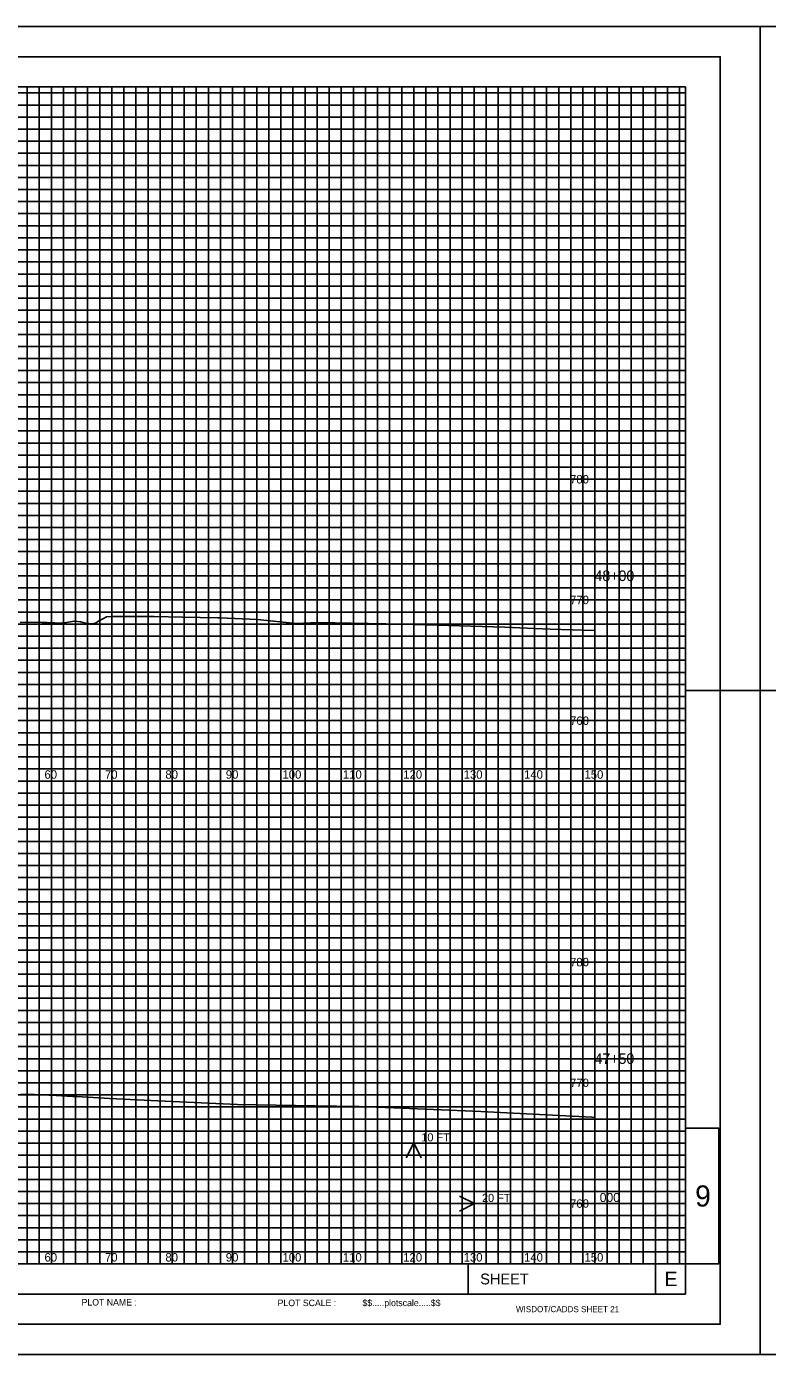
# Model space of a CAD drawing. Extents: x 578243 to 601557, y 174899 to 175559.
# Drawn here: x 600075.7 to 600198.4, y 175338.8 to 175558.8 of the extents above; entities that cross this region are included whole.
import ezdxf

# ---------------------------------------------------------------- set-up
doc = ezdxf.new("R2010")
doc.units = 0
for name, color, linetype in [('E_PROF_Grid', 7, 'Continuous'), ('E_PROF_GridMin', 7, 'Continuous'), ('P_E_XS_Ground', 7, 'Continuous'), ('P_XS_Text', 7, 'Continuous'), ('PLT_Sheet_Border', 7, 'Continuous'), ('PLT_Sheet_Info', 7, 'Continuous')]:
    doc.layers.add(name, color=color, linetype=linetype)

msp = doc.modelspace()

# ---------------------------------------------------------------- linework, layer by layer
at = {"layer": 'E_PROF_Grid'}
for p, q in [((600079.84, 175353.8), (600079.84, 175548.8)), ((600089.84, 175353.8), (600089.84, 175548.8)), ((600099.84, 175353.8), (600099.84, 175548.8)), ((600109.84, 175353.8), (600109.84, 175548.8)), ((600119.84, 175353.8), (600119.84, 175548.8)), ((600129.84, 175353.8), (600129.84, 175548.8)), ((600139.84, 175353.8), (600139.84, 175548.8)), ((600149.84, 175353.8), (600149.84, 175548.8)), ((600159.84, 175353.8), (600159.84, 175548.8)), ((600169.84, 175353.8), (600169.84, 175548.8)), ((600179.84, 175353.8), (600179.84, 175548.8)), ((599869.84, 175543.8), (600184.84, 175543.8)), ((599869.84, 175533.8), (600184.84, 175533.8)), ((599869.84, 175523.8), (600184.84, 175523.8)), ((599869.84, 175513.8), (600184.84, 175513.8)), ((599869.84, 175503.8), (600184.84, 175503.8)), ((599869.84, 175493.8), (600184.84, 175493.8)), ((599869.84, 175483.8), (600184.84, 175483.8)), ((599869.84, 175473.8), (600184.84, 175473.8)), ((599869.84, 175463.8), (600184.84, 175463.8)), ((599869.84, 175453.8), (600184.84, 175453.8)), ((599869.84, 175443.8), (600184.84, 175443.8)), ((599869.84, 175433.8), (600184.84, 175433.8)), ((599869.84, 175423.8), (600184.84, 175423.8)), ((599869.84, 175413.8), (600184.84, 175413.8)), ((599869.84, 175403.8), (600184.84, 175403.8)), ((599869.84, 175393.8), (600184.84, 175393.8)), ((599869.84, 175383.8), (600184.84, 175383.8)), ((599869.84, 175373.8), (600184.84, 175373.8)), ((599869.84, 175363.8), (600184.84, 175363.8))]:
    msp.add_line(p, q, dxfattribs=at)
at = {"layer": 'E_PROF_GridMin'}
for p, q in [((599869.84, 175547.8), (600184.84, 175547.8)), ((600075.84, 175353.8), (600075.84, 175548.8)), ((600077.84, 175353.8), (600077.84, 175548.8)), ((600081.84, 175353.8), (600081.84, 175548.8)), ((600083.84, 175353.8), (600083.84, 175548.8)), ((600085.84, 175353.8), (600085.84, 175548.8)), ((600087.84, 175353.8), (600087.84, 175548.8)), ((600091.84, 175353.8), (600091.84, 175548.8)), ((600093.84, 175353.8), (600093.84, 175548.8)), ((600095.84, 175353.8), (600095.84, 175548.8)), ((600097.84, 175353.8), (600097.84, 175548.8)), ((600101.84, 175353.8), (600101.84, 175548.8)), ((600103.84, 175353.8), (600103.84, 175548.8)), ((600105.84, 175353.8), (600105.84, 175548.8)), ((600107.84, 175353.8), (600107.84, 175548.8)), ((600111.84, 175353.8), (600111.84, 175548.8)), ((600113.84, 175353.8), (600113.84, 175548.8)), ((600115.84, 175353.8), (600115.84, 175548.8)), ((600117.84, 175353.8), (600117.84, 175548.8)), ((600121.84, 175353.8), (600121.84, 175548.8)), ((600123.84, 175353.8), (600123.84, 175548.8)), ((600125.84, 175353.8), (600125.84, 175548.8)), ((600127.84, 175353.8), (600127.84, 175548.8)), ((600131.84, 175353.8), (600131.84, 175548.8)), ((600133.84, 175353.8), (600133.84, 175548.8)), ((600135.84, 175353.8), (600135.84, 175548.8)), ((600137.84, 175353.8), (600137.84, 175548.8)), ((600141.84, 175353.8), (600141.84, 175548.8)), ((600143.84, 175353.8), (600143.84, 175548.8)), ((600145.84, 175353.8), (600145.84, 175548.8)), ((600147.84, 175353.8), (600147.84, 175548.8)), ((600151.84, 175353.8), (600151.84, 175548.8)), ((600153.84, 175353.8), (600153.84, 175548.8)), ((600155.84, 175353.8), (600155.84, 175548.8)), ((600157.84, 175353.8), (600157.84, 175548.8)), ((600161.84, 175353.8), (600161.84, 175548.8)), ((600163.84, 175353.8), (600163.84, 175548.8)), ((600165.84, 175353.8), (600165.84, 175548.8)), ((600167.84, 175353.8), (600167.84, 175548.8)), ((600171.84, 175353.8), (600171.84, 175548.8)), ((600173.84, 175353.8), (600173.84, 175548.8)), ((600175.84, 175353.8), (600175.84, 175548.8)), ((600177.84, 175353.8), (600177.84, 175548.8)), ((600181.84, 175353.8), (600181.84, 175548.8)), ((600183.84, 175353.8), (600183.84, 175548.8)), ((599869.84, 175545.8), (600184.84, 175545.8)), ((599869.84, 175541.8), (600184.84, 175541.8)), ((599869.84, 175539.8), (600184.84, 175539.8)), ((599869.84, 175537.8), (600184.84, 175537.8)), ((599869.84, 175535.8), (600184.84, 175535.8)), ((599869.84, 175531.8), (600184.84, 175531.8)), ((599869.84, 175529.8), (600184.84, 175529.8)), ((599869.84, 175527.8), (600184.84, 175527.8)), ((599869.84, 175525.8), (600184.84, 175525.8)), ((599869.84, 175521.8), (600184.84, 175521.8)), ((599869.84, 175519.8), (600184.84, 175519.8)), ((599869.84, 175517.8), (600184.84, 175517.8)), ((599869.84, 175515.8), (600184.84, 175515.8)), ((599869.84, 175511.8), (600184.84, 175511.8)), ((599869.84, 175509.8), (600184.84, 175509.8)), ((599869.84, 175507.8), (600184.84, 175507.8)), ((599869.84, 175505.8), (600184.84, 175505.8)), ((599869.84, 175501.8), (600184.84, 175501.8)), ((599869.84, 175499.8), (600184.84, 175499.8)), ((599869.84, 175497.8), (600184.84, 175497.8)), ((599869.84, 175495.8), (600184.84, 175495.8)), ((599869.84, 175491.8), (600184.84, 175491.8)), ((599869.84, 175489.8), (600184.84, 175489.8)), ((599869.84, 175487.8), (600184.84, 175487.8)), ((599869.84, 175485.8), (600184.84, 175485.8)), ((599869.84, 175481.8), (600184.84, 175481.8)), ((599869.84, 175479.8), (600184.84, 175479.8)), ((599869.84, 175477.8), (600184.84, 175477.8)), ((599869.84, 175475.8), (600184.84, 175475.8)), ((599869.84, 175471.8), (600184.84, 175471.8)), ((599869.84, 175469.8), (600184.84, 175469.8)), ((599869.84, 175467.8), (600184.84, 175467.8)), ((599869.84, 175465.8), (600184.84, 175465.8)), ((599869.84, 175461.8), (600184.84, 175461.8)), ((599869.84, 175459.8), (600184.84, 175459.8)), ((599869.84, 175457.8), (600184.84, 175457.8)), ((599869.84, 175455.8), (600184.84, 175455.8)), ((599869.84, 175451.8), (600184.84, 175451.8)), ((599869.84, 175449.8), (600184.84, 175449.8)), ((599869.84, 175447.8), (600184.84, 175447.8)), ((599869.84, 175445.8), (600184.84, 175445.8)), ((599869.84, 175441.8), (600184.84, 175441.8)), ((599869.84, 175439.8), (600184.84, 175439.8)), ((599869.84, 175437.8), (600184.84, 175437.8)), ((599869.84, 175435.8), (600184.84, 175435.8)), ((599869.84, 175431.8), (600184.84, 175431.8)), ((599869.84, 175429.8), (600184.84, 175429.8)), ((599869.84, 175427.8), (600184.84, 175427.8)), ((599869.84, 175425.8), (600184.84, 175425.8)), ((599869.84, 175421.8), (600184.84, 175421.8)), ((599869.84, 175419.8), (600184.84, 175419.8)), ((599869.84, 175417.8), (600184.84, 175417.8)), ((599869.84, 175415.8), (600184.84, 175415.8)), ((599869.84, 175411.8), (600184.84, 175411.8)), ((599869.84, 175409.8), (600184.84, 175409.8)), ((599869.84, 175407.8), (600184.84, 175407.8)), ((599869.84, 175405.8), (600184.84, 175405.8)), ((599869.84, 175401.8), (600184.84, 175401.8)), ((599869.84, 175399.8), (600184.84, 175399.8)), ((599869.84, 175397.8), (600184.84, 175397.8)), ((599869.84, 175395.8), (600184.84, 175395.8)), ((599869.84, 175391.8), (600184.84, 175391.8)), ((599869.84, 175389.8), (600184.84, 175389.8)), ((599869.84, 175387.8), (600184.84, 175387.8)), ((599869.84, 175385.8), (600184.84, 175385.8)), ((599869.84, 175381.8), (600184.84, 175381.8)), ((599869.84, 175379.8), (600184.84, 175379.8)), ((599869.84, 175377.8), (600184.84, 175377.8)), ((599869.84, 175375.8), (600184.84, 175375.8)), ((599869.84, 175371.8), (600184.84, 175371.8)), ((599869.84, 175369.8), (600184.84, 175369.8)), ((599869.84, 175367.8), (600184.84, 175367.8)), ((599869.84, 175365.8), (600184.84, 175365.8)), ((599869.84, 175361.8), (600184.84, 175361.8)), ((599869.84, 175359.8), (600184.84, 175359.8)), ((599869.84, 175357.8), (600184.84, 175357.8)), ((599869.84, 175355.8), (600184.84, 175355.8)), ((600197.19, 175338.8), (600197.19, 175348.8)), ((600187.19, 175338.8), (600197.19, 175338.8))]:
    msp.add_line(p, q, dxfattribs=at)
at = {"layer": 'P_E_XS_Ground'}
for points in [[(600074.69, 175460.08), (600078.12, 175460.1), (600078.29, 175460.08), (600079.1, 175460.07), (600081.66, 175459.98), (600083.69, 175460.29), (600084.64, 175460.19), (600085.51, 175459.97), (600086.61, 175459.85), (600087.24, 175460.01), (600087.54, 175460.21), (600087.73, 175460.35), (600088.97, 175461), (600089.93, 175461.05), (600091.95, 175461.07), (600094.72, 175461.04), (600095.78, 175461.04), (600096.84, 175461.05), (600101.53, 175460.94), (600101.57, 175460.94), (600107.42, 175460.84), (600107.69, 175460.82), (600113.97, 175460.58), (600120.34, 175459.92), (600124.09, 175460.06), (600129.48, 175459.98), (600138.07, 175459.81), (600154.91, 175459.31), (600162.4, 175458.96), (600169.84, 175458.73)], [(600074.77, 175381.88), (600075.81, 175381.9), (600080.66, 175381.68), (600083.41, 175381.55), (600084.08, 175381.54), (600089.44, 175381.21), (600097.44, 175380.81), (600110.64, 175380.21), (600123.44, 175379.99), (600130.78, 175379.86), (600136.53, 175379.68), (600150.93, 175379.06), (600169.34, 175378.1), (600169.84, 175378.07)]]:
    msp.add_lwpolyline(points, dxfattribs=at)
at = {"layer": 'PLT_Sheet_Border'}
for points in [[(599857.19, 175338.8), (600197.19, 175338.8), (600197.19, 175558.8), (599857.19, 175558.8)], [(600197.19, 175338.8), (600537.19, 175338.8), (600537.19, 175558.8), (600197.19, 175558.8)], [(599859.59, 175343.8), (600190.59, 175343.8), (600190.59, 175553.8), (599859.59, 175553.8)]]:
    msp.add_lwpolyline(points, close=True, dxfattribs=at)
at = {"layer": 'PLT_Sheet_Info'}
for p, q in [((600187.19, 175558.8), (600197.19, 175558.8)), ((600197.19, 175548.8), (600197.19, 175558.8)), ((600197.19, 175548.8), (600197.19, 175558.8)), ((600197.19, 175558.8), (600207.19, 175558.8)), ((599869.84, 175548.8), (600184.84, 175548.8)), ((600184.84, 175348.8), (600184.84, 175548.8)), ((600197.19, 175443.8), (600197.19, 175453.8)), ((600197.19, 175443.8), (600197.19, 175453.8)), ((600197.19, 175448.8), (600184.84, 175448.8)), ((600197.19, 175448.8), (600209.84, 175448.8)), ((599869.84, 175353.8), (600184.84, 175353.8)), ((600148.84, 175348.8), (600148.84, 175353.8)), ((600179.84, 175348.8), (600179.84, 175353.8)), ((599869.84, 175348.8), (600184.84, 175348.8)), ((600197.19, 175338.8), (600197.19, 175348.8)), ((600197.19, 175338.8), (600207.19, 175338.8))]:
    msp.add_line(p, q, dxfattribs=at)
msp.add_lwpolyline([(600184.84, 175376.3), (600190.34, 175376.3), (600190.34, 175353.8), (600184.84, 175353.8)], close=True, dxfattribs=at)
for points in [[(600139.84, 175373.84), (600138.6, 175371.36)], [(600139.84, 175363.8), (600139.84, 175373.84), (600141.08, 175371.36)], [(600149.89, 175363.8), (600147.4, 175365.04)], [(600139.84, 175363.8), (600149.89, 175363.8), (600147.4, 175362.55)]]:
    msp.add_lwpolyline(points, dxfattribs=at)

# ---------------------------------------------------------------- texts
at = {"layer": 'P_XS_Text'}
for s, height, p in [('780', 1.4, (600165.72, 175483.1)), ('48+00', 1.75, (600169.77, 175466.93)), ('770', 1.4, (600165.72, 175463.1)), ('760', 1.4, (600165.72, 175443.1)), ('60', 1.4, (600078.7, 175434.18)), ('70', 1.4, (600088.71, 175434.18)), ('80', 1.4, (600098.72, 175434.18)), ('90', 1.4, (600108.72, 175434.18)), ('100', 1.4, (600118.1, 175434.18)), ('110', 1.4, (600128.1, 175434.18)), ('120', 1.4, (600138.1, 175434.18)), ('130', 1.4, (600148.1, 175434.18)), ('140', 1.4, (600158.1, 175434.18)), ('150', 1.4, (600168.1, 175434.18)), ('780', 1.4, (600165.72, 175403.1)), ('47+50', 1.75, (600169.77, 175386.93)), ('770', 1.4, (600165.72, 175383.1)), ('760', 1.4, (600165.72, 175363.1)), ('60', 1.4, (600078.7, 175354.19)), ('70', 1.4, (600088.71, 175354.19)), ('80', 1.4, (600098.72, 175354.19)), ('90', 1.4, (600108.72, 175354.19)), ('100', 1.4, (600118.1, 175354.19)), ('110', 1.4, (600128.1, 175354.19)), ('120', 1.4, (600138.1, 175354.19)), ('130', 1.4, (600148.1, 175354.19)), ('140', 1.4, (600158.1, 175354.19)), ('150', 1.4, (600168.1, 175354.19))]:
    msp.add_text(s, height=height, rotation=360, dxfattribs=at).set_placement(p)
at = {"layer": 'PLT_Sheet_Info'}
for s, height, p in [('  10 FT', 1.347, (600140.09, 175374.09)), ('9', 3.5, (600186.42, 175363.3)), ('  20 FT', 1.347, (600150.14, 175364.05)), ('     000', 1.5, (600167.84, 175364.05)), ('SHEET ', 1.8, (600150.84, 175350.4)), ('E', 2.4, (600181.36, 175350.11)), ('PLOT NAME :                      ', 1.08, (600084.84, 175346.9)), ('PLOT SCALE : ', 1.08, (600117.3, 175346.8)), ('$$.....plotscale.....$$', 1.08, (600131.34, 175346.8)), ('WISDOT/CADDS SHEET 21', 1, (600156.76, 175345.8))]:
    msp.add_text(s, height=height, dxfattribs=at).set_placement(p)

doc.saveas('drawing.dxf')
